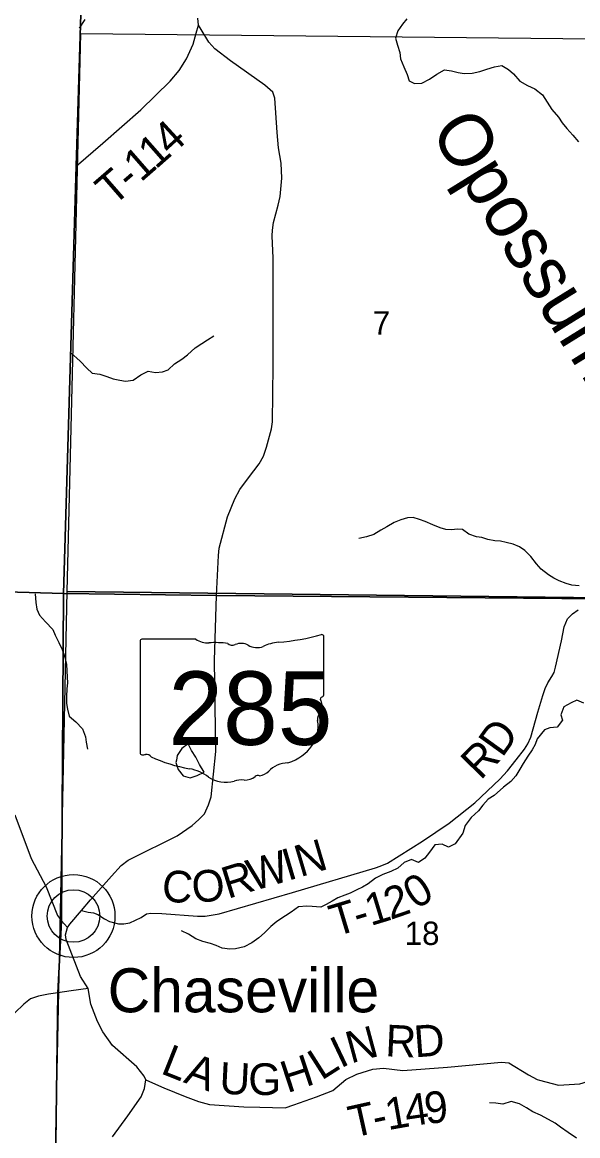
# Model space of a CAD drawing. Extents: x 2043100 to 2470832, y 443715 to 810583.
# Drawn here: x 2258688 to 2263948, y 686553 to 697100 of the extents above; entities that cross this region are included whole.
import ezdxf

# ---------------------------------------------------------------- set-up
doc = ezdxf.new("R2010")
doc.units = 0
for name, color, linetype in [('GM_X_Adjacent_County', 7, 'Continuous'), ('GM_X_County', 7, 'Continuous'), ('GM_X_County_Road', 7, 'Continuous'), ('GM_X_Minor_Lake', 7, 'Continuous'), ('GM_X_Minor_River', 7, 'Continuous'), ('GM_X_Minor_River_Text', 7, 'Continuous'), ('GM_X_Section', 7, 'Continuous'), ('GM_X_Section_Text', 7, 'Continuous'), ('GM_X_State_Location', 7, 'Continuous'), ('GM_X_State_Route', 7, 'Continuous'), ('GM_X_State_Shield', 7, 'Continuous'), ('GM_X_Township', 7, 'Continuous'), ('GM_X_Township_Road', 7, 'Continuous'), ('GM_X_Township_Road_Text', 7, 'Continuous'), ('GM_X_Township_ROW', 7, 'Continuous'), ('GM_X_Unincorporated', 7, 'Continuous'), ('GM_X_Unincorporated_Location', 7, 'Continuous'), ('GM_X_Unincorporated_Text', 7, 'Continuous')]:
    doc.layers.add(name, color=color, linetype=linetype)

msp = doc.modelspace()

# ---------------------------------------------------------------- linework, layer by layer
at = {"layer": 'GM_X_Adjacent_County'}
msp.add_lwpolyline([(2279304, 701805), (2274523, 701941), (2268357, 702066), (2267453, 702102), (2266418, 702131), (2259694, 702266), (2259396, 702227), (2259200, 695737), (2259078, 691690), (2257336, 691739)], dxfattribs=at)
at = {"layer": 'GM_X_County'}
msp.add_lwpolyline([(2257336, 691739), (2259078, 691690), (2259200, 695737), (2259396, 702227), (2259694, 702266), (2266418, 702131), (2267453, 702102), (2268357, 702066), (2274523, 701941), (2279304, 701805)], dxfattribs=at)
at = {"layer": 'GM_X_County_Road'}
msp.add_lwpolyline([(2259311, 687947), (2259151, 687926), (2259026, 687905), (2258938, 687895), (2258842, 687876), (2258767, 687850), (2258702, 687799), (2258618, 687717)], dxfattribs=at)
at = {"layer": 'GM_X_Minor_Lake'}
for points in [[(2260409, 689998), (2260365, 690068), (2260330, 690138), (2260292, 690202), (2260258, 690266), (2260198, 690221), (2260154, 690155), (2260147, 690111)], [(2260147, 690111), (2260143, 690087), (2260163, 690023), (2260211, 689961), (2260279, 689943), (2260345, 689966), (2260409, 689998)]]:
    msp.add_lwpolyline(points, dxfattribs=at)
at = {"layer": 'GM_X_Minor_River'}
for points in [[(2259230, 697044), (2259283, 697127)], [(2262330, 697132), (2262287, 697081), (2262243, 697019), (2262223, 696949), (2262240, 696883), (2262262, 696813), (2262268, 696755), (2262301, 696679), (2262333, 696605), (2262351, 696545), (2262402, 696521), (2262470, 696523), (2262545, 696560), (2262615, 696608), (2262687, 696649), (2262751, 696641), (2262817, 696624), (2262873, 696614), (2262949, 696618), (2263021, 696633), (2263087, 696657), (2263159, 696678), (2263228, 696690), (2263291, 696653), (2263341, 696611), (2263401, 696541), (2263471, 696501), (2263540, 696470)], [(2263540, 696470), (2263614, 696412), (2263658, 696342), (2263703, 696273), (2263767, 696201), (2263799, 696147), (2263844, 696095), (2263900, 696029), (2263956, 695966)], [(2259145, 693971), (2259237, 693889), (2259299, 693823), (2259349, 693777), (2259421, 693768), (2259489, 693746), (2259549, 693722), (2259611, 693709), (2259665, 693699), (2259737, 693711), (2259811, 693760), (2259881, 693794), (2259949, 693781), (2260017, 693789), (2260071, 693807), (2260128, 693864), (2260200, 693910), (2260254, 693951), (2260324, 694015), (2260387, 694056), (2260441, 694092), (2260501, 694130)], [(2263961, 691762), (2263891, 691767), (2263839, 691785), (2263773, 691809), (2263721, 691834), (2263670, 691866), (2263602, 691918), (2263558, 691970), (2263505, 692039), (2263447, 692095), (2263395, 692131), (2263337, 692155), (2263269, 692172), (2263215, 692184), (2263163, 692188), (2263095, 692201), (2263039, 692221), (2262989, 692225), (2262918, 692252), (2262856, 692294), (2262806, 692300), (2262754, 692291), (2262698, 692295), (2262644, 692311), (2262576, 692340), (2262504, 692372), (2262448, 692390), (2262388, 692409), (2262336, 692407), (2262274, 692388), (2262210, 692362), (2262140, 692322), (2262082, 692289), (2262017, 692249), (2261949, 692226), (2261875, 692210)], [(2258811, 691686), (2258815, 691604), (2258825, 691541), (2258852, 691483), (2258908, 691421), (2258976, 691348), (2258999, 691294), (2259035, 691226), (2259065, 691160), (2259092, 691086), (2259106, 691018), (2259110, 690958), (2259113, 690898), (2259115, 690842), (2259111, 690786), (2259106, 690714), (2259108, 690646), (2259116, 690594), (2259133, 690526), (2259195, 690474), (2259257, 690406), (2259288, 690330), (2259294, 690280), (2259306, 690214)], [(2264007, 690651), (2263939, 690678), (2263885, 690652), (2263815, 690615), (2263787, 690541), (2263804, 690489), (2263754, 690423), (2263684, 690418), (2263632, 690398), (2263565, 690313), (2263545, 690259), (2263517, 690207), (2263476, 690147), (2263432, 690080), (2263398, 690024), (2263361, 689962), (2263313, 689909), (2263245, 689853), (2263156, 689776), (2263100, 689740), (2263050, 689683), (2263007, 689629), (2262939, 689567), (2262881, 689492), (2262860, 689420), (2262788, 689319), (2262724, 689287), (2262664, 689315), (2262594, 689308), (2262545, 689240), (2262499, 689182), (2262439, 689141), (2262373, 689169), (2262305, 689142), (2262244, 689086), (2262178, 689055), (2262102, 689027), (2262032, 688992), (2261962, 688938), (2261909, 688908), (2261857, 688881), (2261793, 688849), (2261741, 688831), (2261675, 688806), (2261623, 688774), (2261566, 688743), (2261514, 688719), (2261432, 688723), (2261382, 688728), (2261304, 688720), (2261234, 688671), (2261180, 688635), (2261099, 688582), (2261043, 688536), (2260981, 688474), (2260927, 688427), (2260862, 688381), (2260790, 688342), (2260708, 688324), (2260654, 688320), (2260582, 688329), (2260524, 688355), (2260470, 688374), (2260398, 688394), (2260332, 688418), (2260261, 688463), (2260197, 688495)], [(2263937, 686529), (2263857, 686582), (2263786, 686634), (2263734, 686672), (2263672, 686707), (2263596, 686747), (2263524, 686778), (2263464, 686818), (2263397, 686854), (2263317, 686877), (2263237, 686853), (2263171, 686862), (2263111, 686866)]]:
    msp.add_lwpolyline(points, dxfattribs=at)
at = {"layer": 'GM_X_Section'}
for points in [[(2265025, 696934), (2264970, 691637), (2259112, 691708), (2259244, 696994)], [(2264970, 691637), (2264918, 686308), (2259002, 686407), (2259112, 691708)]]:
    msp.add_lwpolyline(points, close=True, dxfattribs=at)
at = {"layer": 'GM_X_State_Route'}
msp.add_lwpolyline([(2259544, 686543), (2259687, 686742), (2259815, 686920), (2259847, 686999), (2259858, 687083), (2259841, 687118), (2259772, 687207), (2259543, 687407), (2259451, 687536), (2259402, 687635), (2259336, 687800), (2259311, 687947), (2259239, 688062), (2259104, 688412), (2259096, 688456), (2259117, 688524), (2259140, 688558), (2259250, 688687), (2259335, 688786), (2259532, 689010), (2259623, 689111), (2259690, 689162), (2259823, 689230), (2260053, 689344), (2260155, 689395), (2260297, 689491), (2260360, 689548), (2260414, 689602), (2260452, 689687), (2260477, 689763), (2260520, 690193), (2260509, 691053), (2260528, 691671), (2260539, 691923), (2260547, 692050), (2260551, 692120), (2260631, 692414), (2260701, 692585), (2260749, 692673), (2260830, 692784), (2260932, 692917), (2260973, 692991), (2261002, 693074), (2261048, 693250), (2261059, 693314), (2261064, 693847), (2261063, 694865), (2261054, 695076), (2261057, 695132), (2261068, 695204), (2261110, 695369), (2261129, 695451), (2261147, 695623), (2261139, 695764), (2261115, 695910), (2261103, 696057), (2261081, 696380), (2261060, 696438), (2260986, 696505), (2260659, 696734), (2260512, 696848), (2260455, 696911), (2260383, 697030), (2260357, 697074), (2260352, 697140)], dxfattribs=at)
at = {"layer": 'GM_X_State_Shield'}
for p, q in [((2261545, 690729), (2261545, 691281)), ((2259804, 691237), (2259804, 690180)), ((2260331, 691255), (2259822, 691255)), ((2261544, 690729), (2261545, 690729))]:
    msp.add_line(p, q, dxfattribs=at)
for centre, major_axis, start_param, end_param in [((2260925, 692696), (1845, 0), 4.814394, 5.042369), ((2261525, 691284), (19.4, 0), 6.141152, 7.989035), ((2259824, 691239), (20.2, 0), 1.712693, 3.28349), ((2260453, 691378), (196, 0), 4.042523, 4.731795), ((2260517, 690662), (702, 0), 1.404758, 1.657858), ((2260677, 691245), (56.4, 0), 3.836095, 5.185415), ((2260760, 691123), (117, 0), 0.950623, 2.079405), ((2260911, 691290), (141, 0), 4.081561, 5.145723), ((2261160, 690933), (371, 0), 1.699011, 2.107814), ((2261540, 690688), (30, 0), 1.883978, 3.671073), ((2261349, 690618), (180, 0), 5.934695, 6.695948), ((2261524, 690727), (20.7, 0), 5.05454, 6.418171), ((2261614, 690497), (131, 0), 2.387724, 3.262537), ((2261028, 690427), (462, 0), 5.101752, 6.440018), ((2259825, 690178), (20.3, 0), 3.00124, 4.508301), ((2259828, 690286), (155, 0), 4.665946, 4.897461), ((2259859, 690120), (56, 0), 0.519207, 1.627899), ((2260566, 691069), (1333, 0), 4.195997, 4.488961), ((2260169, 689706), (417, 0), 0.823519, 1.323587), ((2260902, 690078), (149, 0), 4.937069, 5.64225), ((2261223, 689884), (253, 0), 1.647645, 2.488434), ((2260620, 690114), (265, 0), 4.026481, 4.996735), ((2260772, 689749), (217, 0), 1.495662, 1.94098), ((2260792, 690035), (141, 0), 4.691044, 5.507374), ((2260919, 689933), (39.7, 0), 1.147584, 2.315152)]:
    msp.add_ellipse(centre, major_axis=major_axis, ratio=0.8, start_param=start_param, end_param=end_param, dxfattribs=at)
at = {"layer": 'GM_X_Township'}
for points in [[(2286381, 691321), (2276850, 691444), (2274138, 691479), (2272743, 691497), (2266029, 691606), (2265625, 691610), (2264826, 691636), (2264209, 691639), (2264161, 691638), (2260528, 691671), (2259078, 691690), (2259200, 695737), (2259396, 702227), (2259694, 702266), (2266418, 702131), (2267453, 702102), (2268357, 702066), (2274523, 701941), (2279304, 701805)], [(2228570, 692450), (2233562, 692283), (2235857, 692235), (2237079, 692186), (2240552, 692108), (2242853, 692061), (2249438, 691906), (2250969, 691851), (2251072, 691849), (2252659, 691828), (2253799, 691787), (2257336, 691739), (2259078, 691690), (2259059, 688587), (2259026, 687905), (2258961, 683177), (2258826, 676651), (2258742, 671669)], [(2258742, 671669), (2258826, 676651), (2258961, 683177), (2259026, 687905), (2259059, 688587), (2259078, 691690), (2260528, 691671), (2264161, 691638), (2264209, 691639), (2264826, 691636), (2265625, 691610), (2266029, 691606), (2272743, 691497), (2274138, 691479), (2276850, 691444), (2286381, 691321), (2287025, 691313), (2290215, 691284), (2290303, 691283), (2291310, 691274), (2291293, 689692), (2291155, 683246), (2291207, 678355), (2291163, 672835)]]:
    msp.add_lwpolyline(points, dxfattribs=at)
at = {"layer": 'GM_X_Township_Road'}
for points in [[(2259200, 695737), (2259451, 695954), (2259812, 696270), (2260088, 696543), (2260175, 696642), (2260243, 696753), (2260305, 696891), (2260336, 696998), (2260357, 697074)], [(2259250, 688687), (2259311, 688670), (2259363, 688665), (2259403, 688647), (2259467, 688606), (2259514, 688583), (2259600, 688560), (2259650, 688559), (2259708, 688569), (2259815, 688621), (2259864, 688655), (2259904, 688662), (2260010, 688659), (2260346, 688633), (2260420, 688632), (2260554, 688654), (2261248, 688858), (2262033, 689092), (2262076, 689107), (2262146, 689135), (2262257, 689205), (2262479, 689343), (2262730, 689512), (2262972, 689705), (2263211, 689931), (2263282, 690008), (2263366, 690113), (2263443, 690216), (2263476, 690266), (2263503, 690328), (2263570, 690565), (2263616, 690723), (2263639, 690789), (2263666, 690843), (2263703, 690902), (2263723, 690940), (2263736, 690990), (2263795, 691240), (2263818, 691372), (2263850, 691448), (2263898, 691496), (2263953, 691534)], [(2258617, 689591), (2258771, 689180), (2258913, 688912), (2259021, 688638), (2259059, 688587), (2259117, 688524)], [(2259858, 687083), (2259920, 687055), (2260028, 687007), (2260231, 686923), (2260358, 686878), (2260460, 686850), (2260787, 686826), (2260937, 686822), (2261179, 686818), (2261260, 686846), (2261474, 686922), (2261628, 686980), (2261752, 687087), (2261856, 687135), (2262008, 687183), (2262110, 687194), (2262292, 687171), (2262715, 687202), (2263226, 687251), (2263296, 687243), (2263480, 687129), (2263565, 687084), (2263587, 687079)]]:
    msp.add_lwpolyline(points, dxfattribs=at)
at = {"layer": 'GM_X_Township_ROW'}
msp.add_lwpolyline([(2263587, 687079), (2263764, 687032), (2263967, 687044), (2264258, 687134), (2264321, 687167), (2264389, 687203), (2264505, 687312), (2264614, 687543), (2264730, 687697), (2264821, 687754), (2264937, 687743), (2265030, 687696), (2265211, 687599), (2265590, 687589), (2266490, 687830), (2266790, 687964), (2266931, 688171), (2267158, 688228), (2267382, 688272), (2267502, 688448)], dxfattribs=at)
at = {"layer": 'GM_X_Unincorporated'}
for radius in [393, 249]:
    msp.add_circle((2259173, 688634), radius, dxfattribs=at)
at = {"layer": 'GM_X_Unincorporated_Location'}
msp.add_line((2259173, 688634), (2259173, 688634), dxfattribs=at)

# ---------------------------------------------------------------- texts
at = {"layer": 'GM_X_Minor_River_Text'}
msp.add_text('Opossum', height=499.9, rotation=301.7945, dxfattribs=at).set_placement((2262542, 696072))
at = {"layer": 'GM_X_Section_Text'}
for s, height, p in [('7', 221, (2262007, 694142)), ('18', 220.8, (2262310, 688360))]:
    msp.add_text(s, height=height, rotation=0, dxfattribs=at).set_placement(p)
at = {"layer": 'GM_X_State_Location'}
for s in ['s', 'r']:
    msp.add_text(s, height=0.0000833, dxfattribs=at).set_placement((2260655, 690639))
msp.add_text('285', height=0.0000833, rotation=0, dxfattribs=at).set_placement((2260302, 690566))
at = {"layer": 'GM_X_State_Shield'}
msp.add_text('285', height=696.1, dxfattribs=at).set_placement((2260072, 690255))
at = {"layer": 'GM_X_Township_Road_Text'}
for s, rotation, p in [('4', 42.4648, (2260094, 695827)), ('1', 41.3476, (2259951, 695701)), ('1', 41.0864, (2259810, 695579)), ('T', 41.0118, (2259548, 695350)), ('-', 41.0345, (2259717, 695497)), ('D', 54.3531, (2263232, 690127)), ('R', 45.4664, (2263027, 689914)), ('N', 16.4648, (2261320, 689001)), ('W', 16.4687, (2260869, 688867)), ('I', 16.4697, (2261202, 688966)), ('C', 355.1271, (2260001, 688776)), ('O', 5.6073, (2260307, 688756)), ('R', 17.2436, (2260634, 688795)), ('0', 32.7325, (2262419, 688690)), ('1', 16.945, (2261986, 688538)), ('2', 19.117, (2262174, 688596)), ('T', 16.746, (2261652, 688437)), ('-', 16.769, (2261867, 688502)), ('N', 15.0877, (2261799, 687236)), ('R', 357.4036, (2262122, 687306)), ('D', 4.166, (2262407, 687295)), ('I', 25.406, (2261701, 687188)), ('L', 338.3745, (2259988, 687147)), ('L', 32.5512, (2261521, 687072)), ('A', 340.1042, (2260206, 687061)), ('U', 357.2322, (2260550, 686952)), ('H', 18.2227, (2261196, 686955)), ('G', 359.8122, (2260828, 686939)), ('4', 8.2192, (2262330, 686637)), ('9', 5.9431, (2262510, 686663)), ('T', 12.5279, (2261815, 686532)), ('1', 10.027, (2262151, 686605)), ('-', 11.7845, (2262033, 686580))]:
    msp.add_text(s, height=300, rotation=rotation, dxfattribs=at).set_placement(p)
at = {"layer": 'GM_X_Unincorporated_Text'}
msp.add_text('Chaseville', height=416.7, rotation=0, dxfattribs=at).set_placement((2259497, 687722))

doc.saveas('drawing.dxf')
